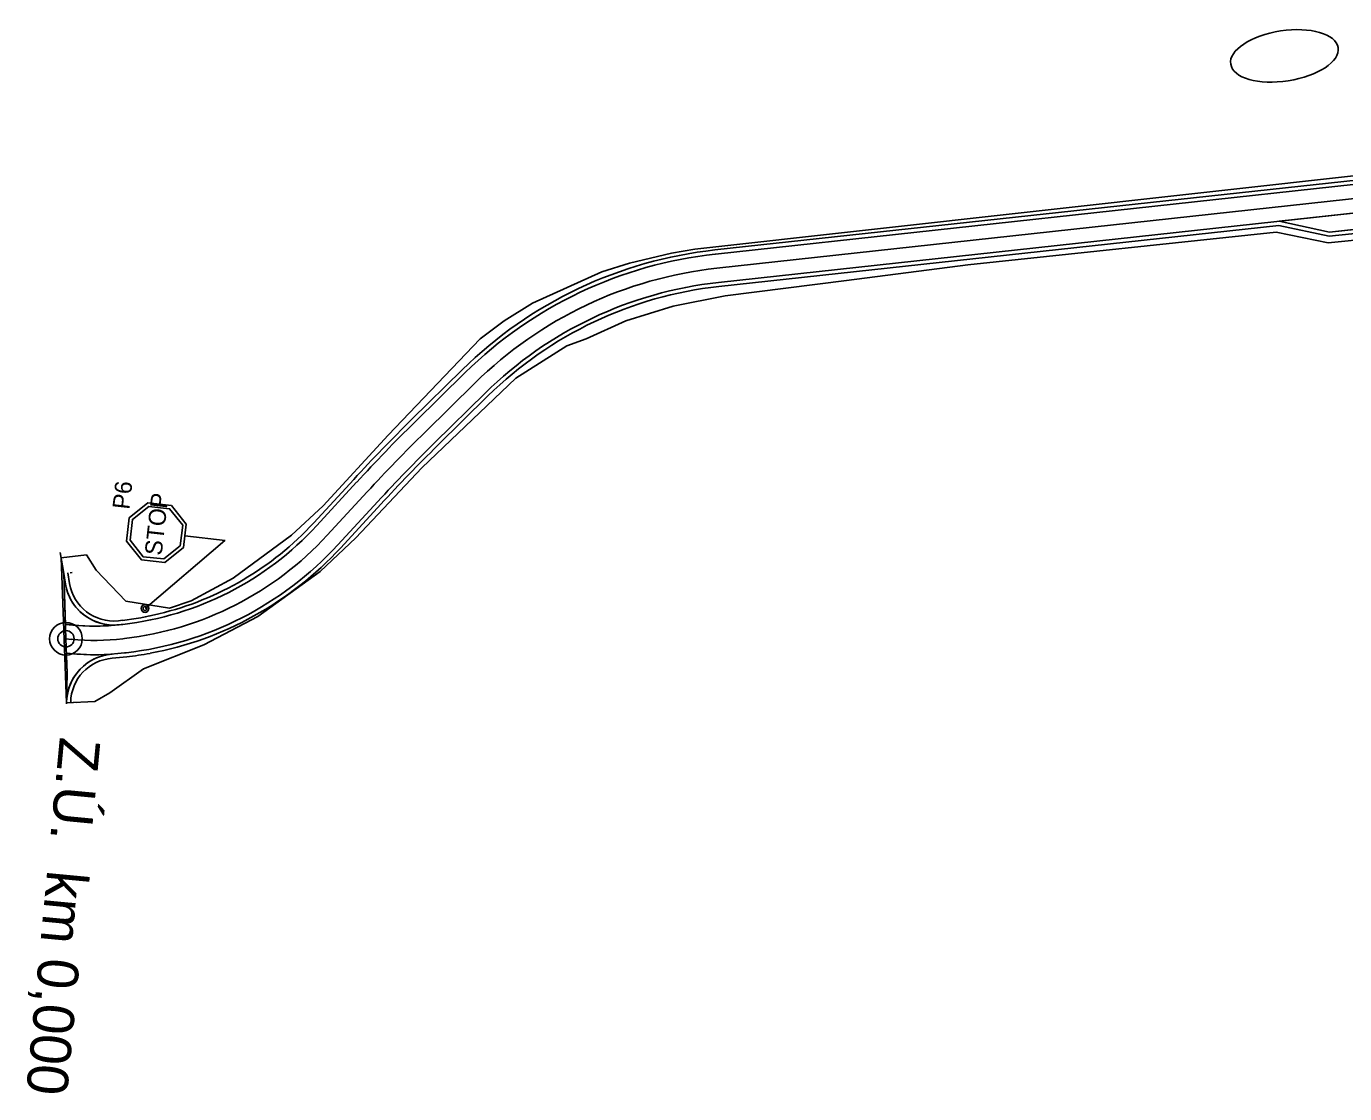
# Model space of a CAD drawing. Extents: x -552278 to -547230, y -1151007 to -1148251.
# Drawn here: x -550339.3 to -550177.8, y -1149855.5 to -1149724.8 of the extents above; entities that cross this region are included whole.
import ezdxf

# ---------------------------------------------------------------- set-up
doc = ezdxf.new("R2010")
doc.units = 0
for name, color, linetype in [('u_HC3a_cesta', 7, 'Continuous'), ('u_HC6_cesta', 7, 'Continuous'), ('u_HC6_osa', 7, 'Continuous'), ('u_HC6_srafa', 7, 'Continuous'), ('u_parcely dotčené stavbou', 7, 'Continuous'), ('u_popis', 7, 'Continuous'), ('u_SDZ', 7, 'Continuous'), ('u_STAVENIŠTĚ', 7, 'Continuous')]:
    doc.layers.add(name, color=color, linetype=linetype)

msp = doc.modelspace()

# ---------------------------------------------------------------- linework, layer by layer
at = {"layer": 'u_HC3a_cesta'}
msp.add_circle((-550324.78, -1149796.13), 0.25, dxfattribs=at)
at = {"layer": 'u_HC6_cesta'}
for p, q in [((-550254.98, -1149752.23), (-550170.3, -1149742.99)), ((-550254.92, -1149752.73), (-550162.95, -1149742.69)), ((-550254.54, -1149756.21), (-550162.57, -1149746.17)), ((-550254.49, -1149756.7), (-550185.89, -1149749.22)), ((-550179.71, -1149750.55), (-550185.89, -1149749.22)), ((-550179.68, -1149750.05), (-550185.86, -1149748.71)), ((-550179.71, -1149750.55), (-550162.3, -1149748.66)), ((-550179.68, -1149750.05), (-550162.35, -1149748.16)), ((-550292.09, -1149772.95), (-550285.92, -1149766.89)), ((-550291.74, -1149773.31), (-550285.57, -1149767.25)), ((-550289.29, -1149775.81), (-550283.12, -1149769.75)), ((-550288.94, -1149776.16), (-550282.77, -1149770.1)), ((-550304.12, -1149785.64), (-550299.22, -1149780.32)), ((-550303.75, -1149785.98), (-550298.86, -1149780.66)), ((-550301.17, -1149788.35), (-550296.28, -1149783.03)), ((-550300.81, -1149788.69), (-550295.91, -1149783.37)), ((-550334.53, -1149793.14), (-550334.73, -1149791.85)), ((-550334.03, -1149793.06), (-550334.24, -1149791.77)), ((-550334.53, -1149798.08), (-550333.63, -1149798.17)), ((-550328.04, -1149797.64), (-550327.55, -1149797.58)), ((-550327.7, -1149798.1), (-550327.49, -1149798.08)), ((-550334.42, -1149801.61), (-550333.96, -1149801.65)), ((-550328.8, -1149802.22), (-550327.03, -1149802.05)), ((-550327.3, -1149801.58), (-550327.08, -1149801.56))]:
    msp.add_line(p, q, dxfattribs=at)
for points in [[(-550335.16, -1149789.29), (-550334.73, -1149791.85), (-550334.47, -1149799.84)], [(-550334.47, -1149799.84), (-550334.34, -1149804.02), (-550334.39, -1149807.41), (-550334.39, -1149807.8)]]:
    msp.add_lwpolyline(points, dxfattribs=at)
for centre, radius, start, end in [((-550249.31, -1149804.17), 52.25, 96.2268, 134.4851), ((-550249.31, -1149804.17), 51.75, 96.2268, 134.4851), ((-550249.31, -1149804.17), 48.25, 96.2268, 134.4851), ((-550249.31, -1149804.17), 47.75, 96.2268, 134.4851), ((-550150.37, -1149917.25), 202.25, 134.4851, 137.3895), ((-550150.37, -1149917.25), 201.75, 134.4851, 137.3895), ((-550150.37, -1149917.25), 198.25, 134.4851, 137.3895), ((-550150.37, -1149917.25), 197.75, 134.4851, 137.3895), ((-550331.9, -1149760.08), 38.25, 276.6262, 317.3895), ((-550331.9, -1149760.08), 37.75, 283.4895, 317.3895), ((-550331.9, -1149760.08), 41.75, 276.6262, 317.3895), ((-550331.9, -1149760.08), 42.25, 280.5426, 317.3895), ((-550328.61, -1149792.17), 6, 189.368, 275.8667), ((-550328.61, -1149792.17), 5.5, 189.368, 275.8667), ((-550330.96, -1149770.04), 28.25, 264.5843, 276.6262), ((-550328.39, -1149807.71), 6, 94.2151, 179.1854), ((-550330.96, -1149770.04), 31.75, 264.5843, 276.6262), ((-550328.39, -1149807.71), 5.5, 94.2151, 179.1854)]:
    msp.add_arc(centre, radius, start, end, dxfattribs=at)
for centre, major_axis, ratio, start_param, end_param in [((-550331.34, -1149766.53), (32.89, 0), 0.950471, 4.828037, 4.965856), ((-550331.66, -1149834.22), (0, 32.21), 0.771195, 6.167537, 6.167537), ((-550331.81, -1149761.04), (41.47, 0), 0.995657, 4.828037, 4.897679)]:
    msp.add_ellipse(centre, major_axis=major_axis, ratio=ratio, start_param=start_param, end_param=end_param, dxfattribs=at)
at = {"layer": 'u_HC6_osa'}
for points in [[(-550254.73, -1149754.47), (-550162.76, -1149744.43)], [(-550290.52, -1149774.56), (-550284.35, -1149768.5)], [(-550302.46, -1149787.17), (-550297.57, -1149781.84)], [(-550334.47, -1149799.84), (-550333.8, -1149799.91)], [(-550327.5, -1149799.84), (-550327.29, -1149799.82)]]:
    msp.add_lwpolyline(points, dxfattribs=at)
for centre, radius, start, end in [((-550249.31, -1149804.17), 50, 96.2268, 134.4851), ((-550150.37, -1149917.25), 200, 134.4851, 137.3895), ((-550331.9, -1149760.08), 40, 276.6262, 317.3895), ((-550330.96, -1149770.04), 30, 264.5843, 276.6262)]:
    msp.add_arc(centre, radius, start, end, dxfattribs=at)
at = {"layer": 'u_HC6_srafa'}
msp.add_line((-550334.4, -1149802.15), (-550334.36, -1149802.12), dxfattribs=at)
for points in [[(-550185.86, -1149748.71), (-550162.57, -1149746.17), (-550154.1, -1149745.06), (-550159.8, -1149747.86), (-550162.35, -1149748.16), (-550171.02, -1149749.1), (-550179.68, -1149750.05), (-550179.68, -1149750.05)], [(-550328.25, -1149798.15), (-550328.03, -1149798.14), (-550327.99, -1149798.14), (-550328.14, -1149798.15), (-550328.61, -1149798.19), (-550329.27, -1149798.24), (-550330.26, -1149798.28), (-550331.6, -1149798.29), (-550333.21, -1149798.2), (-550333.76, -1149798.15), (-550334.53, -1149798.07), (-550334.56, -1149797.01), (-550334.61, -1149795.65), (-550334.73, -1149791.85), (-550334.61, -1149792.65), (-550334.51, -1149793.24), (-550334.44, -1149793.57), (-550334.27, -1149794.14), (-550333.9, -1149794.99), (-550333.61, -1149795.48), (-550333.25, -1149795.96), (-550332.78, -1149796.48), (-550332.33, -1149796.87), (-550331.66, -1149797.33), (-550331.12, -1149797.61), (-550330.37, -1149797.9), (-550329.8, -1149798.05), (-550329.29, -1149798.13), (-550328.84, -1149798.16), (-550328.62, -1149798.17), (-550328.47, -1149798.16)], [(-550331.96, -1149801.78), (-550332.67, -1149801.74), (-550333.14, -1149801.72), (-550333.96, -1149801.65), (-550334.42, -1149801.61), (-550334.4, -1149802.24), (-550334.34, -1149804.02), (-550334.37, -1149805.84), (-550334.37, -1149806.36), (-550334.38, -1149806.66), (-550334.38, -1149806.76), (-550334.38, -1149807.03), (-550334.39, -1149807.2), (-550334.39, -1149807.36), (-550334.3, -1149806.67), (-550334.26, -1149806.44), (-550334.17, -1149806.07), (-550334.1, -1149805.86), (-550333.93, -1149805.39), (-550333.74, -1149804.99), (-550333.57, -1149804.68), (-550333.26, -1149804.2), (-550332.73, -1149803.56), (-550332.34, -1149803.19), (-550331.8, -1149802.76), (-550331.22, -1149802.41), (-550330.74, -1149802.18), (-550330.24, -1149802), (-550329.84, -1149801.88), (-550329.41, -1149801.79), (-550328.83, -1149801.72), (-550329.44, -1149801.76), (-550329.78, -1149801.77), (-550330.42, -1149801.79), (-550330.85, -1149801.79), (-550331.36, -1149801.79)]]:
    msp.add_lwpolyline(points, close=True, dxfattribs=at)
at = {"layer": 'u_parcely dotčené stavbou'}
msp.add_ellipse((-550185.21, -1149728.46), major_axis=(6.58, 1.01), ratio=0.464088, dxfattribs=at)
at = {"layer": 'u_popis'}
for radius in [2, 1]:
    msp.add_circle((-550334.47, -1149799.84), radius, dxfattribs=at)
at = {"layer": 'u_SDZ'}
for p, q in [((-550315.02, -1149787.79), (-550324.78, -1149796.13)), ((-550333.95, -1149791.75), (-550333.7, -1149791.71)), ((-550333.49, -1149807.6), (-550333.24, -1149807.63))]:
    msp.add_line(p, q, dxfattribs=at)
msp.add_lwpolyline([(-550320.08, -1149788.68), (-550319.75, -1149785.8), (-550321.56, -1149783.53), (-550324.45, -1149783.21), (-550326.71, -1149785.02), (-550327.04, -1149787.9), (-550325.23, -1149790.17), (-550322.34, -1149790.49)], close=True, dxfattribs=at)
for points in [[(-550322.34, -1149790.49), (-550320.08, -1149788.68), (-550319.75, -1149785.8), (-550321.56, -1149783.53), (-550324.45, -1149783.21), (-550326.71, -1149785.02), (-550327.04, -1149787.9), (-550325.23, -1149790.17), (-550322.34, -1149790.49)], [(-550320.46, -1149788.47), (-550320.17, -1149785.92), (-550321.77, -1149783.91), (-550324.33, -1149783.63), (-550326.33, -1149785.23), (-550326.62, -1149787.78), (-550325.02, -1149789.79), (-550322.46, -1149790.07), (-550320.46, -1149788.47)], [(-550319.92, -1149787.24), (-550314.95, -1149787.8)]]:
    msp.add_lwpolyline(points, dxfattribs=at)
msp.add_circle((-550324.78, -1149796.13), 0.475, dxfattribs=at)
at = {"layer": 'u_STAVENIŠTĚ'}
for p, q in [((-550169.58, -1149742.36), (-550257.42, -1149752.11)), ((-550179.83, -1149751.37), (-550159.52, -1149749.23)), ((-550223.98, -1149754.04), (-550186.2, -1149750.05)), ((-550186.2, -1149750.05), (-550179.83, -1149751.37)), ((-550260.27, -1149752.6), (-550265.43, -1149753.84)), ((-550257.42, -1149752.11), (-550260.27, -1149752.6)), ((-550265.43, -1149753.84), (-550268.84, -1149754.89)), ((-550238.84, -1149755.95), (-550223.98, -1149754.04)), ((-550268.84, -1149754.89), (-550277.3, -1149758.75)), ((-550253.7, -1149757.85), (-550238.84, -1149755.95)), ((-550277.3, -1149758.75), (-550280.79, -1149760.92)), ((-550265.89, -1149760.91), (-550260.1, -1149759.11)), ((-550260.1, -1149759.11), (-550253.7, -1149757.85)), ((-550280.79, -1149760.92), (-550283.71, -1149763.1)), ((-550270.74, -1149763.09), (-550265.89, -1149760.91)), ((-550283.71, -1149763.1), (-550294.98, -1149774.9)), ((-550279.36, -1149767.91), (-550273.12, -1149763.95)), ((-550273.12, -1149763.95), (-550270.74, -1149763.09)), ((-550290.88, -1149778.91), (-550279.36, -1149767.91)), ((-550294.98, -1149774.9), (-550302.96, -1149783.57)), ((-550298.95, -1149787.46), (-550290.88, -1149778.91)), ((-550302.96, -1149783.57), (-550306.85, -1149787.14)), ((-550306.85, -1149787.14), (-550314, -1149792.43)), ((-550303.34, -1149791.59), (-550298.95, -1149787.46)), ((-550331.96, -1149789.55), (-550335.05, -1149789.94)), ((-550335.05, -1149789.94), (-550334.39, -1149807.69)), ((-550330.75, -1149791.45), (-550331.96, -1149789.55)), ((-550327.12, -1149795.22), (-550330.75, -1149791.45)), ((-550310.97, -1149797.1), (-550303.34, -1149791.59)), ((-550314, -1149792.43), (-550319.13, -1149795.19)), ((-550321.8, -1149796.11), (-550327.12, -1149795.22)), ((-550319.13, -1149795.19), (-550321.8, -1149796.11)), ((-550317.56, -1149800.6), (-550310.97, -1149797.1)), ((-550324.96, -1149803.54), (-550317.56, -1149800.6)), ((-550329.11, -1149806.45), (-550324.96, -1149803.54)), ((-550334.39, -1149807.69), (-550330.95, -1149807.51)), ((-550330.95, -1149807.51), (-550329.11, -1149806.45))]:
    msp.add_line(p, q, dxfattribs=at)

# ---------------------------------------------------------------- texts
at = {"layer": 'u_popis'}
msp.add_text('Z.Ú.  km 0,000', height=5, rotation=264.5843, dxfattribs=at).set_placement((-550335.21, -1149811.8))
at = {"layer": 'u_SDZ'}
for s, p in [('P6', (-550326.7, -1149784.07)), ('STOP', (-550322.75, -1149789.71))]:
    msp.add_text(s, height=2.1, rotation=83.5956, dxfattribs=at).set_placement(p)

doc.saveas('drawing.dxf')
